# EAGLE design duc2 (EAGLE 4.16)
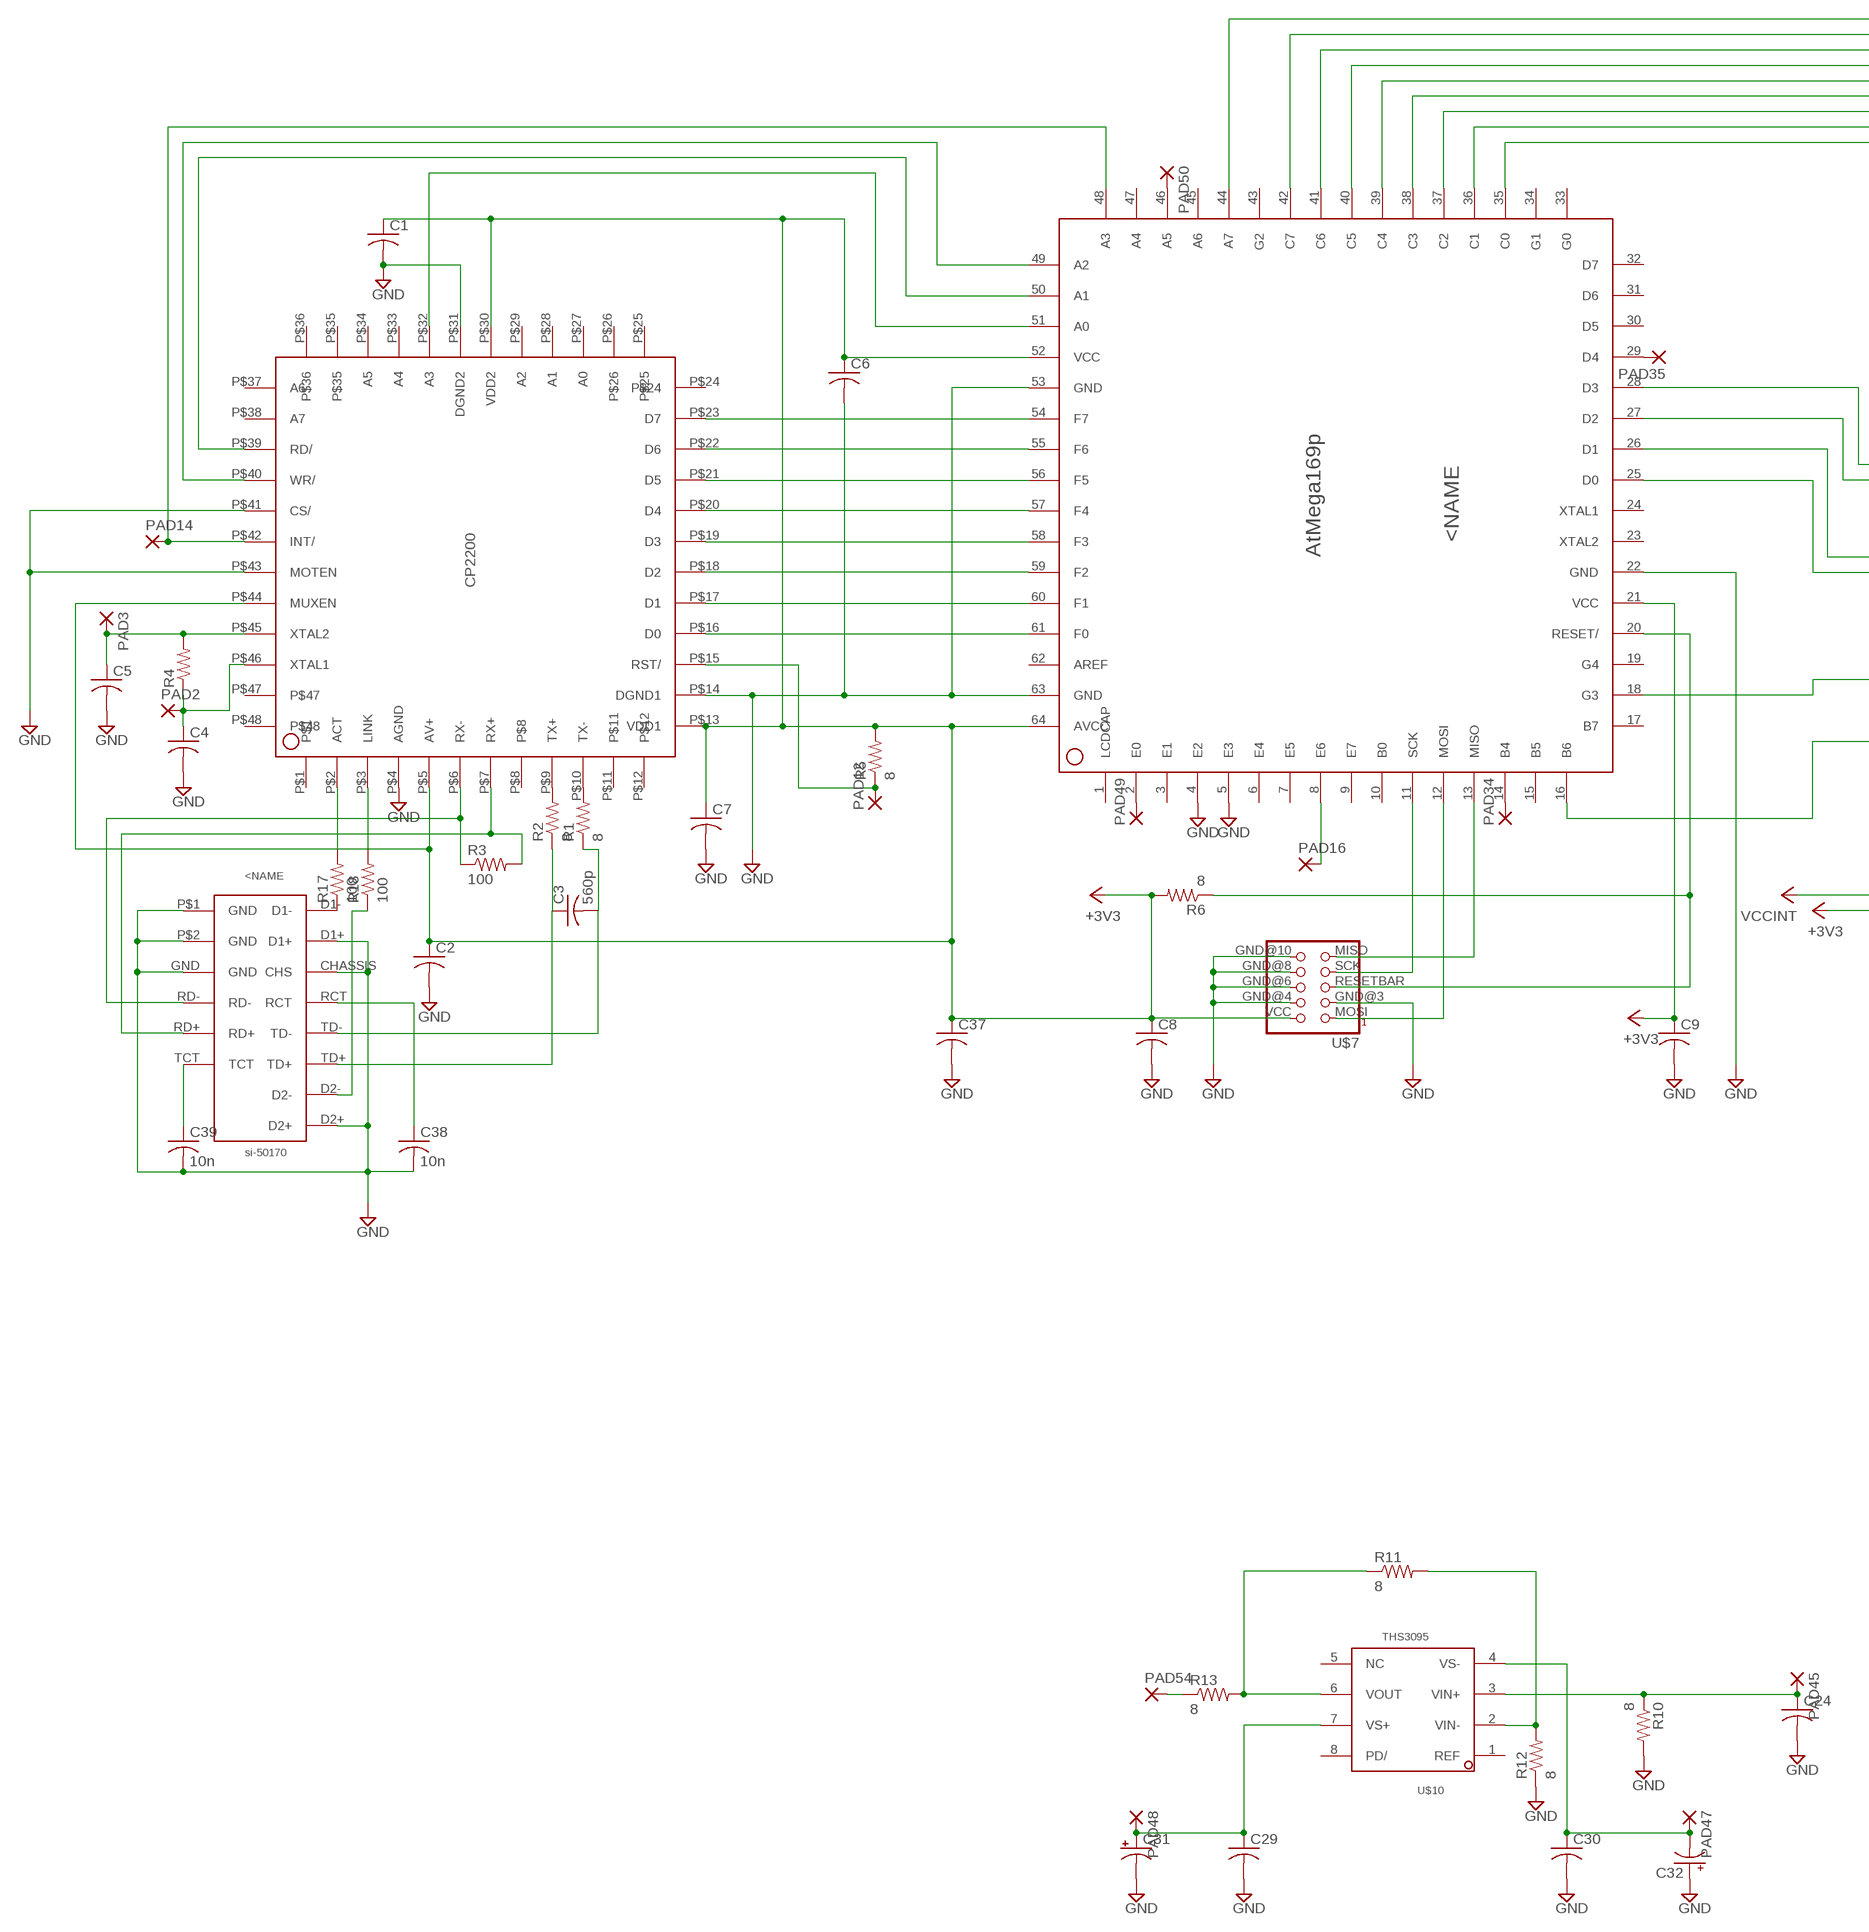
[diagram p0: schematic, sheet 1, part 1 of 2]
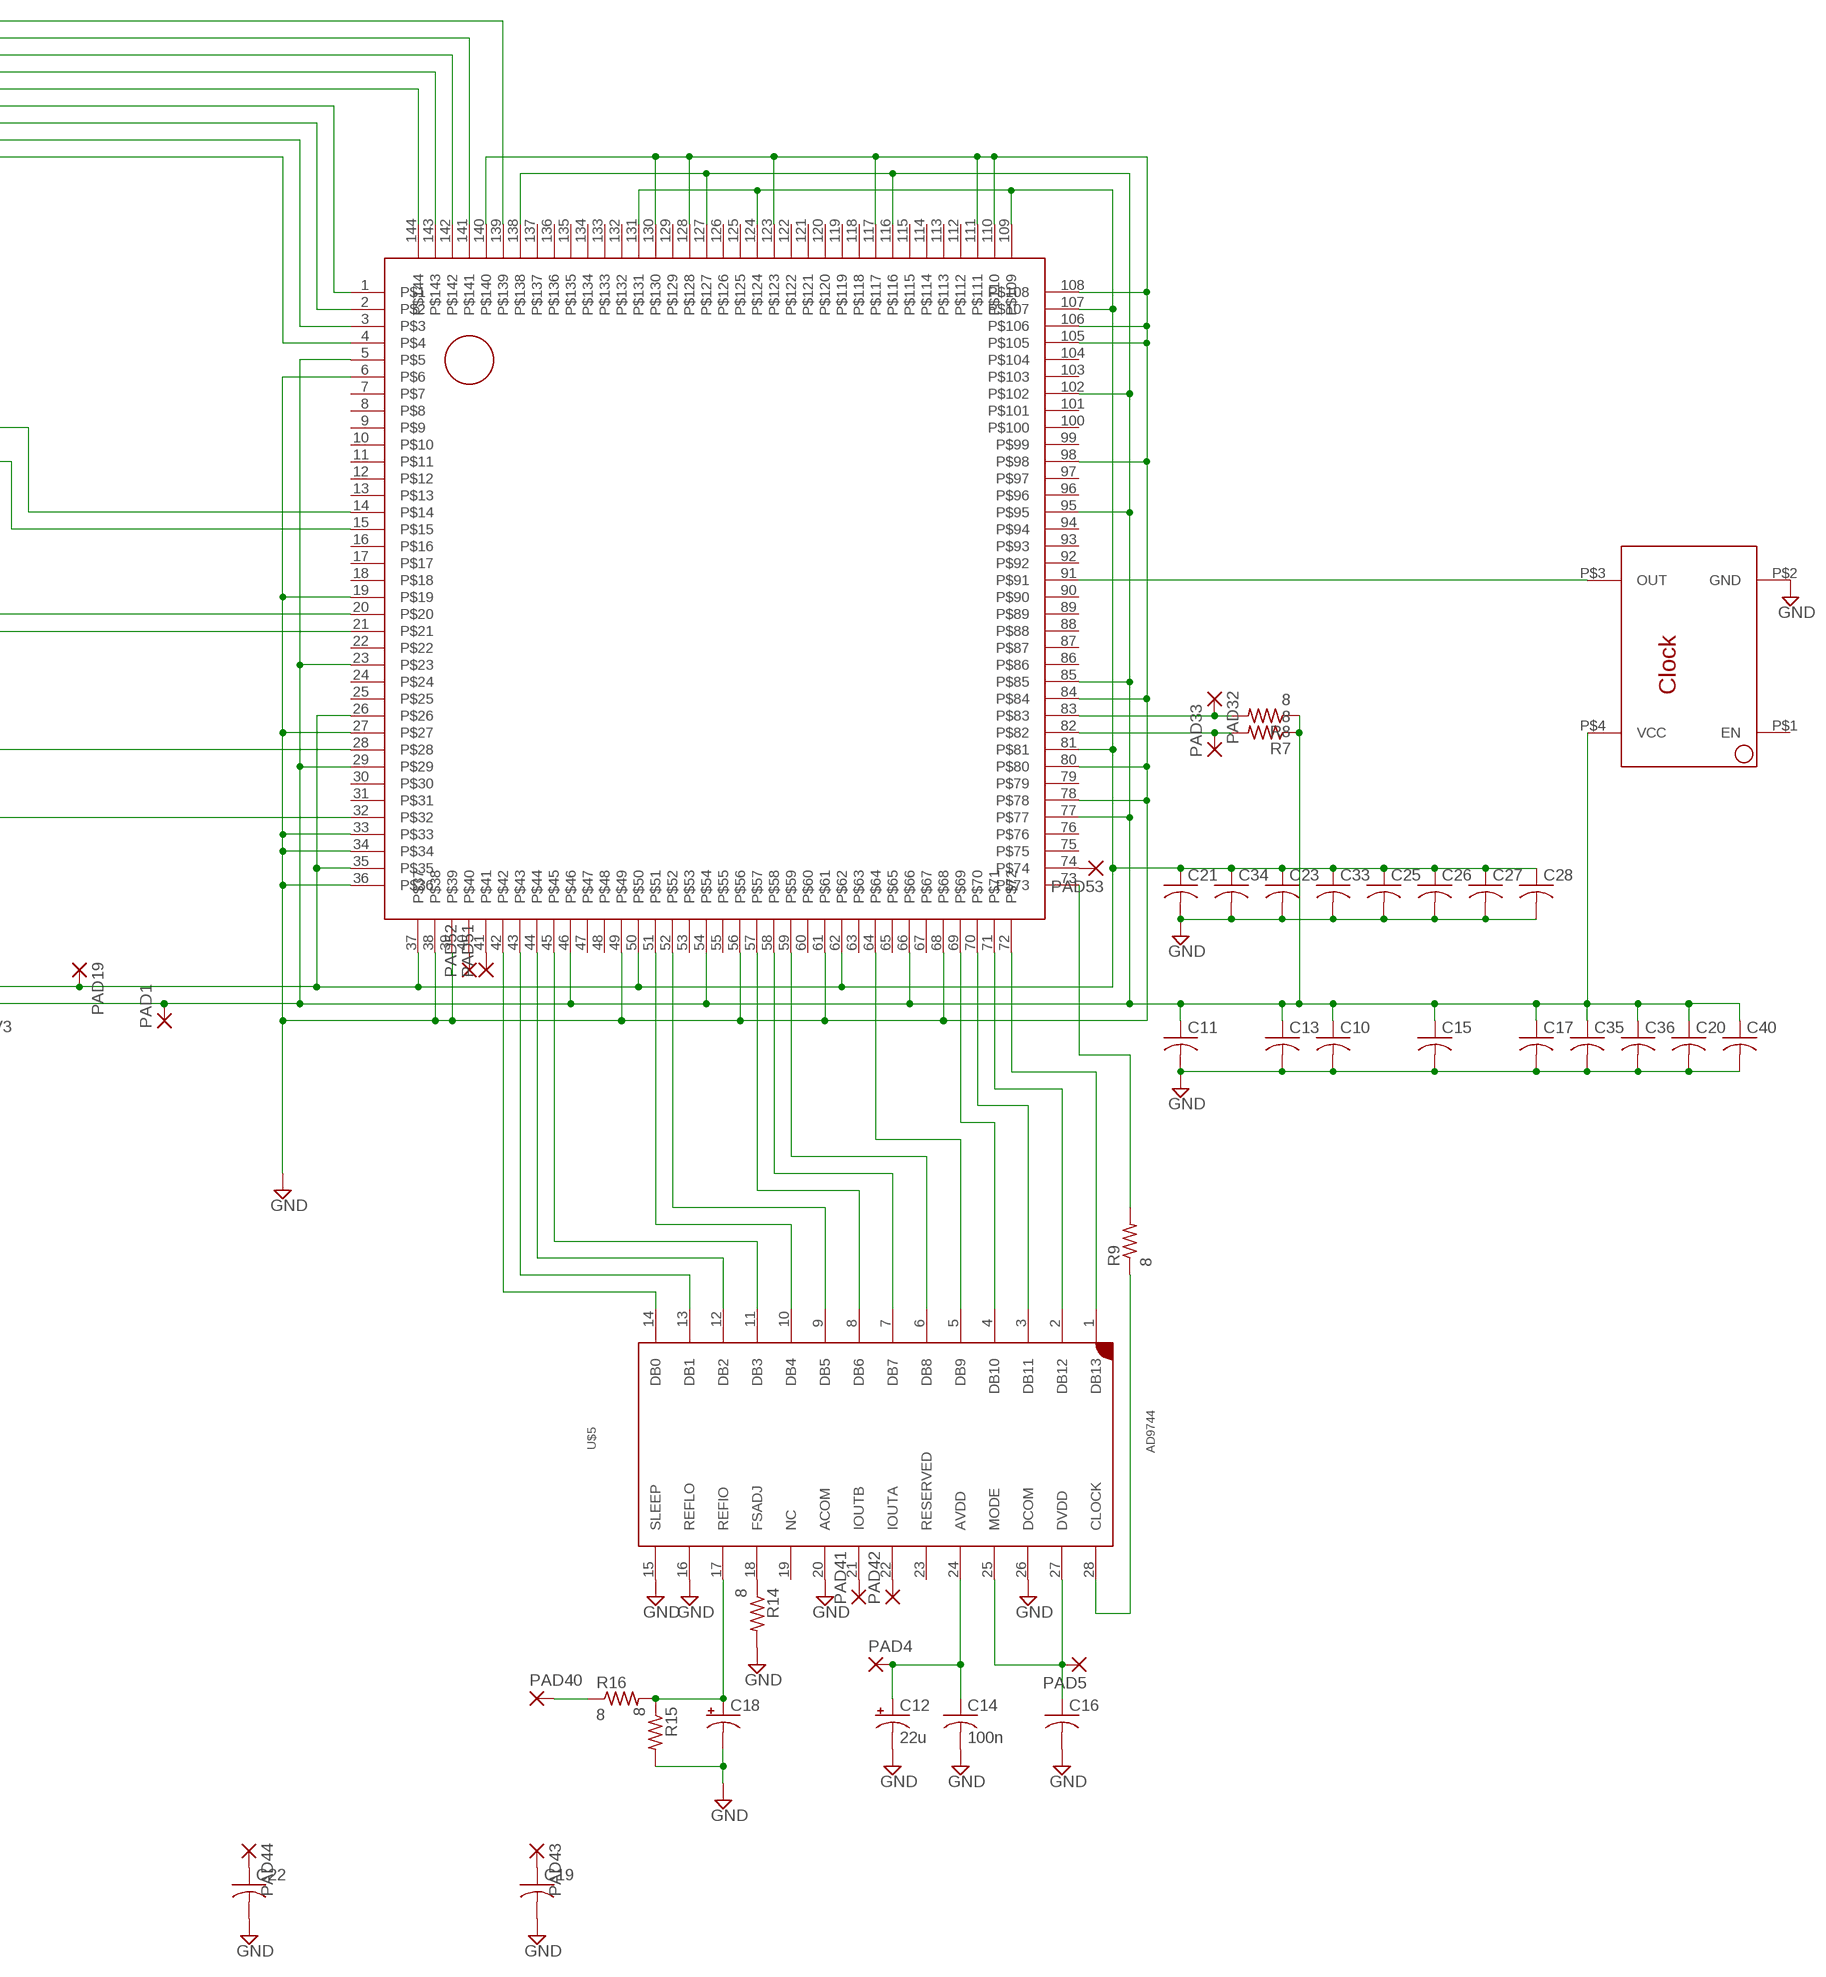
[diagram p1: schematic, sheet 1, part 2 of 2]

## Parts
C1  C-USC0805  [C0805]
C2  C-USC0805  [C0805]
C3  560p  C-USC1206  [C1206]
C4  C-USC1206  [C1206]
C5  C-USC1206  [C1206]
C6  C-USC0805  [C0805]
C7  C-USC0805  [C0805]
C8  C-USC0805  [C0805]
C9  C-USC0805  [C0805]
C10  C-USC0805  [C0805]
C11  C-USC0805  [C0805]
C12  22u  CPOL-USSMCB  [SMC_B]
C13  C-USC0805  [C0805]
C14  100n  C-USC0805  [C0805]
C15  C-USC0805  [C0805]
C16  C-USC0805  [C0805]
C17  C-USC0805  [C0805]
C18  CPOL-USSMCB  [SMC_B]
C19  C-USC1206  [C1206]
C20  C-USC0805  [C0805]
C21  C-USC0805  [C0805]
C22  C-USC1206  [C1206]
C23  C-USC0805  [C0805]
C24  C-USC1206  [C1206]
C25  C-USC0805  [C0805]
C26  C-USC0805  [C0805]
C27  C-USC0805  [C0805]
C28  C-USC0805  [C0805]
C29  C-USC0805  [C0805]
C30  C-USC0805  [C0805]
C31  CPOL-USD/7343-31W  [D/7343-31W]
C32  CPOL-USD/7343-31W  [D/7343-31W]
C33  C-USC0805  [C0805]
C34  C-USC0805  [C0805]
C35  C-USC0805  [C0805]
C36  C-USC0805  [C0805]
C37  C-USC0805  [C0805]
C38  10n  C-USC1206  [C1206]
C39  10n  C-USC1206  [C1206]
C40  C-USC0805  [C0805]
PAD1  SMD2  [SMD2]
PAD2  SMD2  [SMD2]
PAD3  SMD2  [SMD2]
PAD4  SMD2  [SMD2]
PAD5  SMD2  [SMD2]
PAD12  SMD2  [SMD2]
PAD14  SMD2  [SMD2]
PAD16  SMD2  [SMD2]
PAD19  SMD2  [SMD2]
PAD32  SMD2  [SMD2]
PAD33  SMD2  [SMD2]
PAD34  SMD2  [SMD2]
PAD35  SMD2  [SMD2]
PAD40  SMD2  [SMD2]
PAD41  SMD2  [SMD2]
PAD42  SMD2  [SMD2]
PAD43  SMD2  [SMD2]
PAD44  SMD2  [SMD2]
PAD45  SMD2  [SMD2]
PAD47  1,6/0,8  [1,6/0,8]
PAD48  1,6/0,8  [1,6/0,8]
PAD49  SMD2  [SMD2]
PAD50  SMD2  [SMD2]
PAD51  SMD2  [SMD2]
PAD52  SMD2  [SMD2]
PAD53  SMD2  [SMD2]
PAD54  SMD2  [SMD2]
R1  8  R-US_R1206  [R1206]
R2  8  R-US_R1206  [R1206]
R3  100  R-US_R1206  [R1206]
R4  R-US_R1206  [R1206]
R5  8  R-US_R1206  [R1206]
R6  8  R-US_R1206  [R1206]
R7  8  R-US_R1206  [R1206]
R8  8  R-US_R1206  [R1206]
R9  8  R-US_R1206  [R1206]
R10  8  R-US_R1206  [R1206]
R11  8  R-US_R1206  [R1206]
R12  8  R-US_R1206  [R1206]
R13  8  R-US_R1206  [R1206]
R14  8  R-US_R1206  [R1206]
R15  8  R-US_R1206  [R1206]
R16  8  R-US_R1206  [R1206]
R17  100  R-US_R1206  [R1206]
R18  100  R-US_R1206  [R1206]
U$1  CP2200  [MQFP48]
U$2  MEGA169P  [TQFP64]
U$3  EP2C8  [TQFP144]
U$4  MAGJACK2  [MAGJACK2]
U$5  AD9744  [TSSOP28]
U$6  CLOCKCB3  [CLOCKSMD]
U$7  AVR-ISP2X5SMD  [2X5SMD]
U$10  THS3095  [SOIC-8]

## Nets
+3V3: C1.1 C2.1 C6.1 C7.1 C8.1 C9.1 C10.1 C11.1 C13.1 C15.1 C17.1 C20.1 C35.1 C36.1 C37.1 C40.1 PAD1.1(P) R5.2 R6.2 R7.1 R8.1 U$1.P$5(AV+) U$1.P$13(VDD1) U$1.P$30(VDD2) U$1.P$44(MUXEN) U$2.21(VCC) U$2.52(VCC) U$2.64(AVCC) U$3.5 U$3.23 U$3.29 U$3.46 U$3.54 U$3.66 U$3.77 U$3.85 U$3.95 U$3.102 U$3.116 U$3.127 U$3.138 U$6.P$4(VCC) U$7.VCC
GND: C1.2 C2.2 C4.2 C5.2 C6.2 C7.2 C8.2 C9.2 C10.2 C11.2 C12.- C13.2 C14.2 C15.2 C16.2 C17.2 C18.- C19.2 C20.2 C21.2 C22.2 C23.2 C24.2 C25.2 C26.2 C27.2 C28.2 C29.2 C30.2 C31.- C32.+ C33.2 C34.2 C35.2 C36.2 C37.2 C38.2 C39.2 C40.2 R10.2 R12.1 R14.2 R15.2 U$1.P$4(AGND) U$1.P$14(DGND1) U$1.P$31(DGND2) U$1.P$41(CS/) U$1.P$43(MOTEN) U$2.4(E2) U$2.5(E3) U$2.22(GND) U$2.53(GND) U$2.63(GND) U$3.6 U$3.19 U$3.27 U$3.33 U$3.34 U$3.36 U$3.38 U$3.39 U$3.49 U$3.56 U$3.61 U$3.68 U$3.78 U$3.80 U$3.84 U$3.98 U$3.105 U$3.106 U$3.108 U$3.110 U$3.111 U$3.117 U$3.123 U$3.128 U$3.130 U$3.140 U$4.CHASSIS(CHS) U$4.D1+ U$4.D2+ U$4.GND U$4.P$1(GND) U$4.P$2(GND) U$5.15(SLEEP) U$5.16(REFLO) U$5.20(ACOM) U$5.26(DCOM) U$6.P$2(GND) U$7.GND@3 U$7.GND@4 U$7.GND@6 U$7.GND@8 U$7.GND@10
N$1: R1.2 U$1.P$10(TX-)
N$2: R2.2 U$1.P$9(TX+)
N$3: R17.1 U$4.D1-
N$4: PAD12.1(P) R5.1 U$1.P$15(RST/)
N$5: C16.1 PAD5.1(P) U$5.25(MODE) U$5.27(DVDD)
N$7: C5.1 PAD3.1(P) R4.2 U$1.P$45(XTAL2)
N$8: U$1.P$16(D0) U$2.61(F0)
N$9: R17.2 U$1.P$2(ACT)
N$10: C3.2 R1.1 U$4.TD-
N$11: R3.2 U$1.P$7(RX+) U$4.RD+
N$12: R18.1 U$4.D2-
N$13: C3.1 R2.1 U$4.TD+
N$14: U$1.P$17(D1) U$2.60(F1)
N$15: C4.1 PAD2.1(P) R4.1 U$1.P$46(XTAL1)
N$16: U$1.P$18(D2) U$2.59(F2)
N$17: U$1.P$19(D3) U$2.58(F3)
N$18: U$1.P$20(D4) U$2.57(F4)
N$19: U$1.P$21(D5) U$2.56(F5)
N$20: U$1.P$22(D6) U$2.55(F6)
N$21: U$1.P$23(D7) U$2.54(F7)
N$22: U$1.P$39(RD/) U$2.50(A1)
N$23: U$1.P$40(WR/) U$2.49(A2)
N$24: PAD14.1(P) U$1.P$42(INT/) U$2.48(A3)
N$26: R18.2 U$1.P$3(LINK)
N$27: U$2.13(MISO) U$7.MISO
N$28: U$2.11(SCK) U$7.SCK
N$29: U$2.12(MOSI) U$7.MOSI
N$30: R6.1 U$2.20(RESET/) U$7.RESETBAR
N$31: PAD16.1(P) U$2.8(E6)
N$32: PAD33.1(P) R7.2 U$3.82
N$33: PAD32.1(P) R8.2 U$3.83
N$34: U$1.P$32(A3) U$2.51(A0)
N$35: U$2.26(D1) U$3.20
N$36: U$2.27(D2) U$3.15
N$37: U$2.28(D3) U$3.14
N$38: U$2.44(A7) U$3.139
N$39: U$2.42(C7) U$3.141
N$40: U$2.41(C6) U$3.142
N$41: U$2.40(C5) U$3.143
N$42: R3.1 U$1.P$6(RX-) U$4.RD-
N$43: U$2.39(C4) U$3.144
N$44: U$2.38(C3) U$3.1
N$45: U$2.37(C2) U$3.2
N$46: U$2.36(C1) U$3.3
N$47: U$2.35(C0) U$3.4
N$48: PAD34.1(P) U$2.14(B4)
N$49: PAD35.1(P) U$2.29(D4)
N$50: U$3.91 U$6.P$3(OUT)
N$51: U$3.45 U$5.11(DB3)
N$52: U$3.43 U$5.13(DB1)
N$53: U$3.58 U$5.7(DB7)
N$54: U$3.59 U$5.6(DB8)
N$55: U$3.64 U$5.5(DB9)
N$56: U$3.44 U$5.12(DB2)
N$57: U$3.72 U$5.1(DB13)
N$58: R9.2 U$3.73
N$59: PAD51.1(P) U$3.41
N$60: U$3.52 U$5.9(DB5)
N$61: U$3.69 U$5.4(DB10)
N$62: U$3.57 U$5.8(DB6)
N$63: U$3.42 U$5.14(DB0)
N$64: U$3.51 U$5.10(DB4)
N$65: U$3.70 U$5.3(DB11)
N$66: U$3.71 U$5.2(DB12)
N$67: R9.1 U$5.28(CLOCK)
N$68: U$2.25(D0) U$3.21
N$69: U$2.18(G3) U$3.28
N$70: U$2.16(B6) U$3.32
N$71: C18.+ R15.1 R16.2 U$5.17(REFIO)
N$72: C12.+ C14.1 PAD4.1(P) U$5.24(AVDD)
N$74: R14.1 U$5.18(FSADJ)
N$75: PAD41.1(P) U$5.21(IOUTB)
N$76: PAD42.1(P) U$5.22(IOUTA)
N$77: C19.1 PAD43.1(P)
N$78: C22.1 PAD44.1(P)
N$79: C29.1 C31.+ PAD48.1(P) U$10.7(VS+)
N$80: C24.1 PAD45.1(P) R10.1 U$10.3(VIN+)
N$81: C30.1 C32.- PAD47.1(P) U$10.4(VS-)
N$82: R11.2 R12.2 U$10.2(VIN-)
N$83: R11.1 R13.2 U$10.6(VOUT)
N$84: PAD49.1(P) U$2.2(E0)
N$86: PAD50.1(P) U$2.46(A5)
N$88: C39.1 U$4.TCT
N$89: PAD52.1(P) U$3.40
N$90: PAD53.1(P) U$3.74
N$91: PAD54.1(P) R13.1
N$92: PAD40.1(P) R16.1
N$93: C38.1 U$4.RCT
VCCINT: C21.1 C23.1 C25.1 C26.1 C27.1 C28.1 C33.1 C34.1 PAD19.1(P) U$3.26 U$3.35 U$3.37 U$3.50 U$3.62 U$3.81 U$3.107 U$3.109 U$3.124 U$3.131
Unconnected: U$1.P$1 U$1.P$8 U$1.P$11 U$1.P$12 U$1.P$24 U$1.P$25 U$1.P$26 U$1.P$27(A0) U$1.P$28(A1) U$1.P$29(A2) U$1.P$33(A4) U$1.P$34(A5) U$1.P$35 U$1.P$36 U$1.P$37(A6) U$1.P$38(A7) U$1.P$47 U$1.P$48 U$2.1(LCDCAP) U$2.3(E1) U$2.6(E4) U$2.7(E5) U$2.9(E7) U$2.10(B0) U$2.15(B5) U$2.17(B7) U$2.19(G4) U$2.23(XTAL2) U$2.24(XTAL1) U$2.30(D5) U$2.31(D6) U$2.32(D7) U$2.33(G0) U$2.34(G1) U$2.43(G2) U$2.45(A6) U$2.47(A4) U$3.7 U$3.8 U$3.9 U$3.10 U$3.11 U$3.12 U$3.13 U$3.16 U$3.17 U$3.18 U$3.22 U$3.24 U$3.25 U$3.30 U$3.31 U$3.47 U$3.48 U$3.53 U$3.55 U$3.60 U$3.63 U$3.65 U$3.67 U$3.75 U$3.76 U$3.79 U$3.86 U$3.87 U$3.88 U$3.89 U$3.90 U$3.92 U$3.93 U$3.94 U$3.96 U$3.97 U$3.99 U$3.100 U$3.101 U$3.103 U$3.104 U$3.112 U$3.113 U$3.114 U$3.115 U$3.118 U$3.119 U$3.120 U$3.121 U$3.122 U$3.125 U$3.126 U$3.129 U$3.132 U$3.133 U$3.134 U$3.135 U$3.136 U$3.137 U$5.19(NC) U$5.23(RESERVED) U$6.P$1(EN) U$10.1(REF) U$10.5(NC) U$10.8(PD/)

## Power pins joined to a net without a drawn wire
AREF: U$2.62(AREF)

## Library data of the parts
C1-C11 C13-C17 C19-C30 C33-C40 = rcl:C-US: CAPACITOR, American symbol
C12 C18 C31 C32 = rcl:CPOL-US: POLARIZED CAPACITOR, American symbol
PAD1-PAD5 PAD12 PAD14 PAD16 PAD19 PAD32-PAD35 PAD40-PAD45 PAD49-PAD54 = wirepad:SMD2: SMD PAD
PAD47 PAD48 = wirepad:1,6/0,8: THROUGH-HOLE PAD
R1-R18 = rcl:R-US_: RESISTOR, American symbol
U$1 = Jim:CP2200
U$2 = Jim:MEGA169P
U$3 = Jim:EP2C8
U$4 = Jim:MAGJACK2
U$5 = Jim:AD9744
U$6 = Jim:CLOCKCB3
U$7 = Jim:AVR-ISP
U$10 = Jim:THS3095

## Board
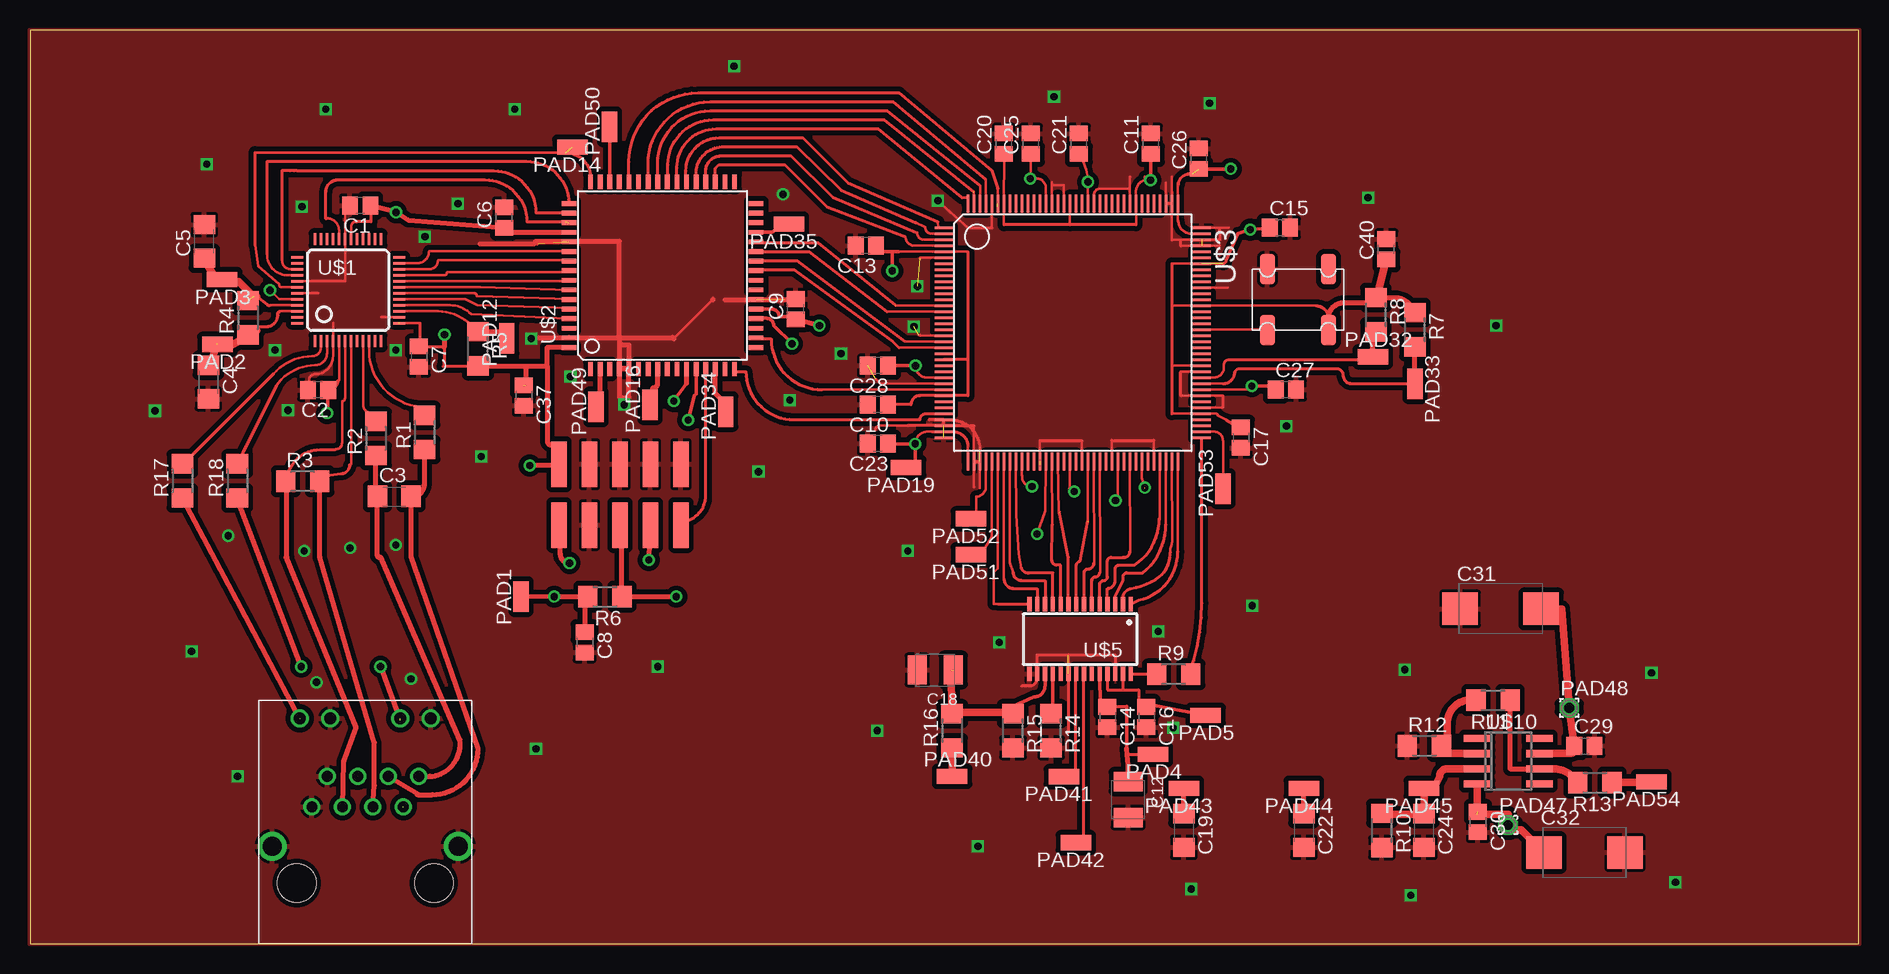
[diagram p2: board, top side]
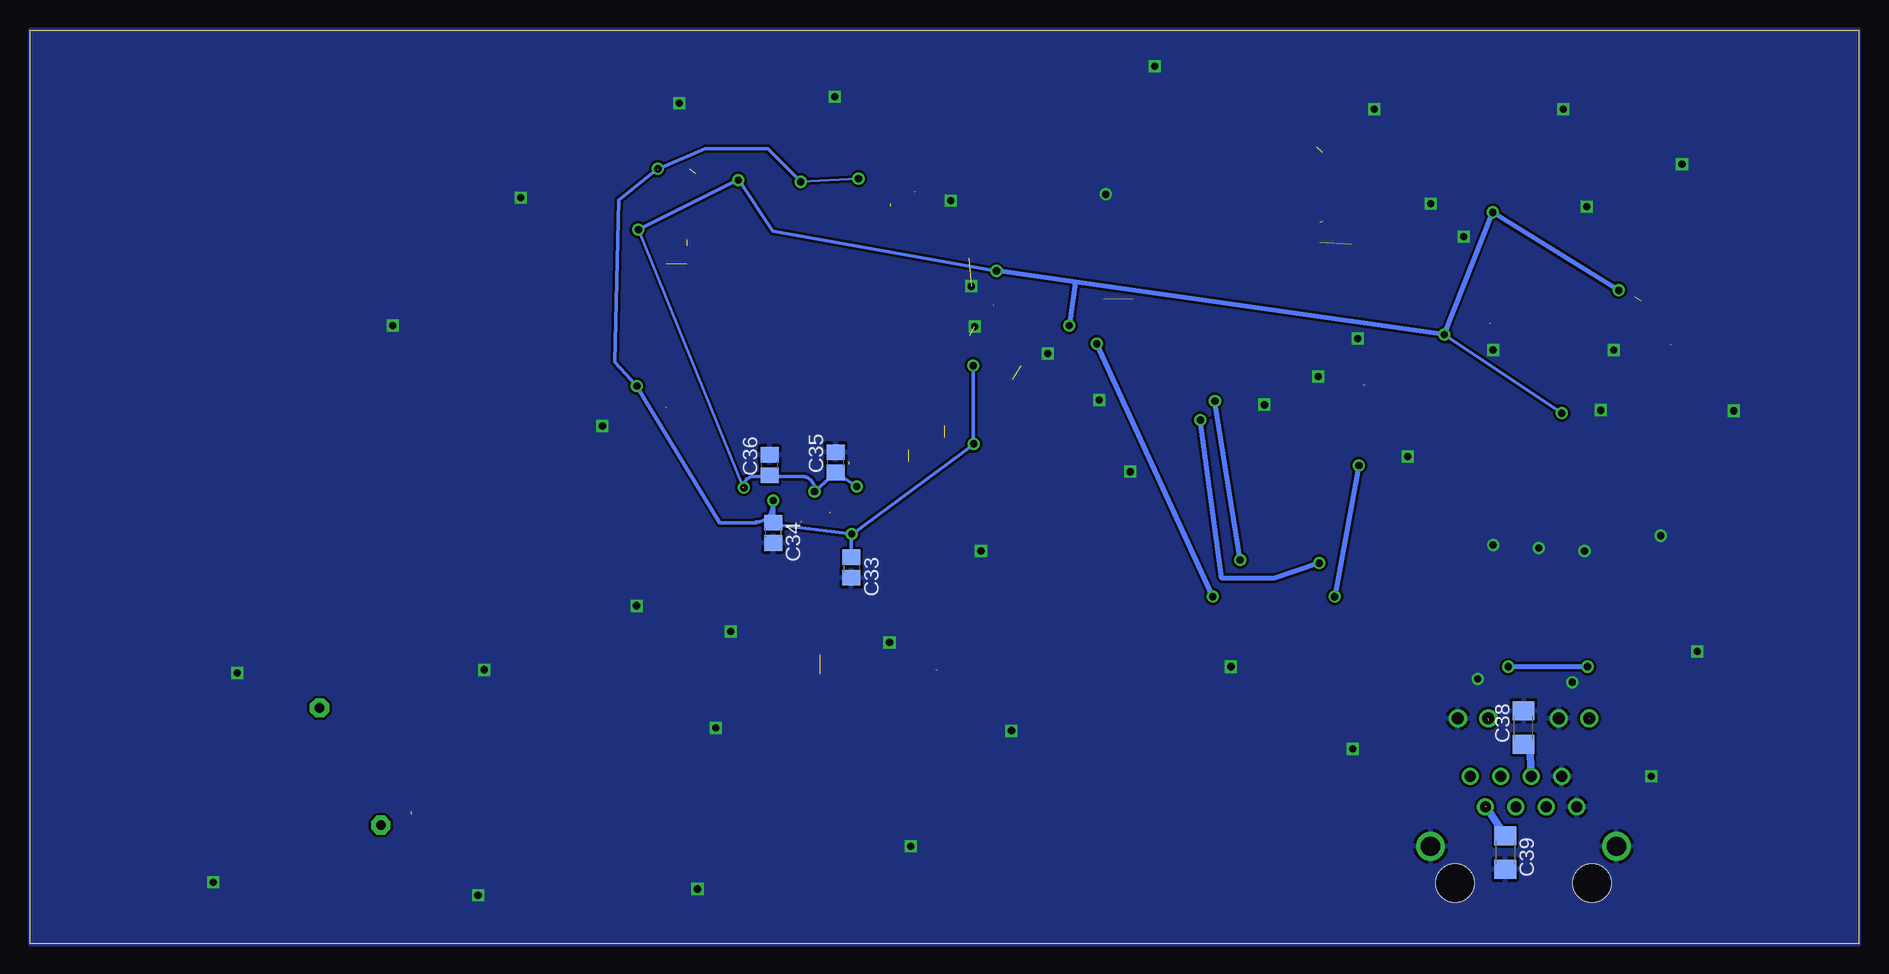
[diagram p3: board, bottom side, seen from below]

Size 152.4 x 76.2 mm. Coordinates in mm from the lower left corner, seen from the top.
Outline: 0,0 152.4,0 152.4,76.2 0,76.2 0,0
Copper layers (1*16): Top 0.035mm / dielectric 1.5mm / Bottom 0.035mm
Design rules "Jim": minimum track width 8mil, minimum drill 20mil, track to track 8mil, track to pad 8mil, pad to pad 8mil, via to via 8mil, smd to smd 8mil, copper to edge 0mil, drill to drill 10mil, minimum pad ring 10mil, minimum via ring 8mil, stop-mask expansion 0mil, vias tented up to drill 0mil, thermal gap 10mil

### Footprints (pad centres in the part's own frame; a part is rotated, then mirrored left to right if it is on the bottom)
C0805 = smd 1.3 x 1.5: 1 -0.85,0; 2 0.85,0
C1206 = smd 1.6 x 1.8: 1 -1.4,0; 2 1.4,0
SMC_B = smd 1.6 x 2.4: + -1.5,0; - 1.5,0
D/7343-31W = smd 2.95 x 2.7: + 3.375,0; - -3.375,0
SMD2 = smd 1.27 x 2.54: 1 0,0
1,6/0,8 = drill 0.813 pad 1.6 octagon: 1 0,0
R1206 = smd 1.6 x 1.803: 1 -1.422,0; 2 1.422,0
MQFP48 = smd 0.22 x 1: P$1 -2.75,-4.25; P$2 -2.25,-4.25; P$3 -1.75,-4.25; P$4 -1.25,-4.25; P$5 -0.75,-4.25; P$6 -0.25,-4.25; P$7 0.25,-4.25; P$8 0.75,-4.25; P$9 1.25,-4.25; P$10 1.75,-4.25; P$11 2.25,-4.25; P$12 2.75,-4.25; P$25 2.75,4.25; P$26 2.25,4.25; P$27 1.75,4.25; P$28 1.25,4.25; P$29 0.75,4.25; P$30 0.25,4.25; P$31 -0.25,4.25; P$32 -0.75,4.25; P$33 -1.25,4.25; P$34 -1.75,4.25; P$35 -2.25,4.25; P$36 -2.75,4.25 | smd 1 x 0.22: P$13 4.25,-2.75; P$14 4.25,-2.25; P$15 4.25,-1.75; P$16 4.25,-1.25; P$17 4.25,-0.75; P$18 4.25,-0.25; P$19 4.25,0.25; P$20 4.25,0.75; P$21 4.25,1.25; P$22 4.25,1.75; P$23 4.25,2.25; P$24 4.25,2.75; P$37 -4.25,2.75; P$38 -4.25,2.25; P$39 -4.25,1.75; P$40 -4.25,1.25; P$41 -4.25,0.75; P$42 -4.25,0.25; P$43 -4.25,-0.25; P$44 -4.25,-0.75; P$45 -4.25,-1.25; P$46 -4.25,-1.75; P$47 -4.25,-2.25; P$48 -4.25,-2.75
TQFP64 = smd 1.194 x 0.4: 1 -7.8,6; 2 -7.8,5.2; 3 -7.8,4.4; 4 -7.8,3.6; 5 -7.8,2.8; 6 -7.8,2; 7 -7.8,1.2; 8 -7.8,0.4; 9 -7.8,-0.4; 10 -7.8,-1.2; 11 -7.8,-2; 12 -7.8,-2.8; 13 -7.8,-3.6; 14 -7.8,-4.4; 15 -7.8,-5.2; 16 -7.8,-6; 33 7.8,-6; 34 7.8,-5.2; 35 7.8,-4.4; 36 7.8,-3.6; 37 7.8,-2.8; 38 7.8,-2; 39 7.8,-1.2; 40 7.8,-0.4; 41 7.8,0.4; 42 7.8,1.2; 43 7.8,2; 44 7.8,2.8; 45 7.8,3.6; 46 7.8,4.4; 47 7.8,5.2; 48 7.8,6 | smd 0.4 x 1.194: 17 -6,-7.8; 18 -5.2,-7.8; 19 -4.4,-7.8; 20 -3.6,-7.8; 21 -2.8,-7.8; 22 -2,-7.8; 23 -1.2,-7.8; 24 -0.4,-7.8; 25 0.4,-7.8; 26 1.2,-7.8; 27 2,-7.8; 28 2.8,-7.8; 29 3.6,-7.8; 30 4.4,-7.8; 31 5.2,-7.8; 32 6,-7.8; 49 6,7.8; 50 5.2,7.8; 51 4.4,7.8; 52 3.6,7.8; 53 2.8,7.8; 54 2,7.8; 55 1.2,7.8; 56 0.4,7.8; 57 -0.4,7.8; 58 -1.2,7.8; 59 -2,7.8; 60 -2.8,7.8; 61 -3.6,7.8; 62 -4.4,7.8; 63 -5.2,7.8; 64 -6,7.8
TQFP144 = smd 0.22 x 1.5: 1 -8.75,-10.75; 2 -8.25,-10.75; 3 -7.75,-10.75; 4 -7.25,-10.75; 5 -6.75,-10.75; 6 -6.25,-10.75; 7 -5.75,-10.75; 8 -5.25,-10.75; 9 -4.75,-10.75; 10 -4.25,-10.75; 11 -3.75,-10.75; 12 -3.25,-10.75; 13 -2.75,-10.75; 14 -2.25,-10.75; 15 -1.75,-10.75; 16 -1.25,-10.75; 17 -0.75,-10.75; 18 -0.25,-10.75; 19 0.25,-10.75; 20 0.75,-10.75; 21 1.25,-10.75; 22 1.75,-10.75; 23 2.25,-10.75; 24 2.75,-10.75; 25 3.25,-10.75; 26 3.75,-10.75; 27 4.25,-10.75; 28 4.75,-10.75; 29 5.25,-10.75; 30 5.75,-10.75; 31 6.25,-10.75; 32 6.75,-10.75; 33 7.25,-10.75; 34 7.75,-10.75; 35 8.25,-10.75; 36 8.75,-10.75; 73 8.75,10.75; 74 8.25,10.75; 75 7.75,10.75; 76 7.25,10.75; 77 6.75,10.75; 78 6.25,10.75; 79 5.75,10.75; 80 5.25,10.75; 81 4.75,10.75; 82 4.25,10.75; 83 3.75,10.75; 84 3.25,10.75; 85 2.75,10.75; 86 2.25,10.75; 87 1.75,10.75; 88 1.25,10.75; 89 0.75,10.75; 90 0.25,10.75; 91 -0.25,10.75; 92 -0.75,10.75; 93 -1.25,10.75; 94 -1.75,10.75; 95 -2.25,10.75; 96 -2.75,10.75; 97 -3.25,10.75; 98 -3.75,10.75; 99 -4.25,10.75; 100 -4.75,10.75; 101 -5.25,10.75; 102 -5.75,10.75; 103 -6.25,10.75; 104 -6.75,10.75; 105 -7.25,10.75; 106 -7.75,10.75; 107 -8.25,10.75; 108 -8.75,10.75 | smd 1.5 x 0.22: 37 10.75,-8.75; 38 10.75,-8.25; 39 10.75,-7.75; 40 10.75,-7.25; 41 10.75,-6.75; 42 10.75,-6.25; 43 10.75,-5.75; 44 10.75,-5.25; 45 10.75,-4.75; 46 10.75,-4.25; 47 10.75,-3.75; 48 10.75,-3.25; 49 10.75,-2.75; 50 10.75,-2.25; 51 10.75,-1.75; 52 10.75,-1.25; 53 10.75,-0.75; 54 10.75,-0.25; 55 10.75,0.25; 56 10.75,0.75; 57 10.75,1.25; 58 10.75,1.75; 59 10.75,2.25; 60 10.75,2.75; 61 10.75,3.25; 62 10.75,3.75; 63 10.75,4.25; 64 10.75,4.75; 65 10.75,5.25; 66 10.75,5.75; 67 10.75,6.25; 68 10.75,6.75; 69 10.75,7.25; 70 10.75,7.75; 71 10.75,8.25; 72 10.75,8.75; 109 -10.75,8.75; 110 -10.75,8.25; 111 -10.75,7.75; 112 -10.75,7.25; 113 -10.75,6.75; 114 -10.75,6.25; 115 -10.75,5.75; 116 -10.75,5.25; 117 -10.75,4.75; 118 -10.75,4.25; 119 -10.75,3.75; 120 -10.75,3.25; 121 -10.75,2.75; 122 -10.75,2.25; 123 -10.75,1.75; 124 -10.75,1.25; 125 -10.75,0.75; 126 -10.75,0.25; 127 -10.75,-0.25; 128 -10.75,-0.75; 129 -10.75,-1.25; 130 -10.75,-1.75; 131 -10.75,-2.25; 132 -10.75,-2.75; 133 -10.75,-3.25; 134 -10.75,-3.75; 135 -10.75,-4.25; 136 -10.75,-4.75; 137 -10.75,-5.25; 138 -10.75,-5.75; 139 -10.75,-6.25; 140 -10.75,-6.75; 141 -10.75,-7.25; 142 -10.75,-7.75; 143 -10.75,-8.25; 144 -10.75,-8.75
MAGJACK2 = drill 0.9 round: CHASSIS 8.89,3.175; GND 6.35,4.445; RCT 8.89,0.635; RD+ 6.35,-0.635; RD- 6.35,1.905; TCT 6.35,-3.175; TD+ 8.89,-4.445; TD- 8.89,-1.905 | drill 1 round: D1+ 13.716,2.921; D1- 13.716,5.461; D2+ 13.716,-5.461; D2- 13.716,-2.921 | drill 1.6 round: P$1 3.048,7.747; P$2 3.048,-7.747 | hole 3.2: 0,5.715; 0,-5.715
TSSOP28 = smd 0.35 x 1.2: 1 -4.225,-2.9; 2 -3.575,-2.9; 3 -2.925,-2.9; 4 -2.275,-2.9; 5 -1.625,-2.9; 6 -0.975,-2.9; 7 -0.325,-2.9; 8 0.325,-2.9; 9 0.975,-2.9; 10 1.625,-2.9; 11 2.275,-2.9; 12 2.925,-2.9; 13 3.575,-2.9; 14 4.225,-2.9; 15 4.225,2.9; 16 3.575,2.9; 17 2.925,2.9; 18 2.275,2.9; 19 1.625,2.9; 20 0.975,2.9; 21 0.325,2.9; 22 -0.325,2.9; 23 -0.975,2.9; 24 -1.625,2.9; 25 -2.275,2.9; 26 -2.925,2.9; 27 -3.575,2.9; 28 -4.225,2.9
CLOCKSMD = smd 1.27 x 2.54: P$1 -2.54,-2.54; P$2 2.54,-2.54; P$3 2.54,2.54; P$4 -2.54,2.54
2X5SMD = smd 1.27 x 3.81: GND@3 -2.54,-2.54; GND@4 -2.54,2.54; GND@6 0,2.54; GND@8 2.54,2.54; GND@10 5.08,2.54; MISO 5.08,-2.54; MOSI -5.08,-2.54; RESETBAR 0,-2.54; SCK 2.54,-2.54; VCC -5.08,2.54
SOIC-8 = smd 0.6 x 2.2: 1 -1.905,-2.6; 2 -0.635,-2.6; 3 0.635,-2.6; 4 1.905,-2.6; 5 1.905,2.6; 6 0.635,2.6; 7 -0.635,2.6; 8 -1.905,2.6

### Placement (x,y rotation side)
C1  27.51,61.56 180 top
C2  24,46.19 180 top
C3  30.35,37.32 0 top
C4  14.87,46.85 270 top
C5  14.53,58.57 90 top
C6  39.51,60.56 90 top
C7  32.41,48.96 270 top
C8  46.23,25.15 270 top
C9  63.81,52.91 90 top
C10  70.66,44.96 180 top
C11  93.41,66.71 90 top
C12  91.51,12.03 270 top
C13  69.66,58.21 180 top
C14  89.78,18.91 270 top
C15  104.16,59.71 0 top
C16  93.03,18.91 270 top
C17  100.91,42.21 270 top
C18  75.43,22.84 180 top
C19  96.16,9.46 270 top
C20  81.16,66.71 90 top
C21  87.41,66.71 90 top
C22  106.16,9.46 270 top
C23  70.66,41.71 180 top
C24  116.16,9.46 270 top
C25  83.41,66.71 90 top
C26  97.41,65.46 90 top
C27  104.66,46.21 0 top
C28  70.66,48.21 180 top
C29  129.54,16.51 0 top
C30  120.65,10.16 270 top
C31  122.56,27.94 0 top
C32  129.54,7.62 0 top
C33  83.95,31.38 270 bottom
C34  90.48,34.28 270 bottom
C35  85.27,40.15 90 bottom
C36  90.75,39.92 90 bottom
C37  41.15,45.72 270 top
C38  27.94,18.03 90 bottom
C39  29.46,7.62 270 bottom
C40  113.03,57.91 90 top
PAD1  40.92,28.97 0 top
PAD2  15.62,50 90 top
PAD3  16.01,55.39 90 top
PAD4  93.58,15.81 90 top
PAD5  97.97,19.06 90 top
PAD12  39.72,50.51 0 top
PAD14  45.19,66.42 90 top
PAD16  51.66,44.96 0 top
PAD19  73.01,39.72 90 top
PAD32  111.91,48.96 270 top
PAD33  115.41,46.71 180 top
PAD34  57.97,44.38 0 top
PAD35  63.24,60.02 90 top
PAD40  76.83,13.97 270 top
PAD41  86.16,13.96 90 top
PAD42  87.16,8.46 90 top
PAD43  96.16,12.97 90 top
PAD44  106.16,12.97 90 top
PAD45  116.16,12.97 90 top
PAD47  123.16,9.91 0 top
PAD48  128.27,19.68 0 top
PAD49  47.17,44.78 0 top
PAD50  48.29,68.12 0 top
PAD51  78.41,32.46 90 top
PAD52  78.41,35.46 90 top
PAD53  99.41,37.96 0 top
PAD54  135.11,13.52 90 top
R1  32.89,42.65 90 top
R2  28.83,42.15 90 top
R3  22.73,38.57 0 top
R4  18.16,52.21 90 top
R5  37.33,49.63 270 top
R6  47.91,28.96 180 top
R7  115.41,51.21 270 top
R8  112.16,52.46 270 top
R9  95.31,22.48 0 top
R10  112.66,9.46 270 top
R11  121.92,20.32 180 top
R12  116.2,16.51 0 top
R13  130.41,13.46 180 top
R14  85.09,17.78 270 top
R15  81.92,17.78 270 top
R16  76.83,17.78 90 top
R17  12.7,38.61 90 top
R18  17.27,38.61 90 top
U$1  26.5,54.5 0 top
U$2  52.71,55.73 90 top
U$3  86.91,50.96 270 top
U$4  27.94,5.08 90 top
U$5  87.51,25.41 180 top
U$6  105.66,53.71 180 top
U$7  49.16,37.46 0 top
U$10  123.19,15.24 270 top

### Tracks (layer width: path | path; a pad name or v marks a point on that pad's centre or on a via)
+3V3  (via drill 0.6)  (4 unrouted)
  Top 0.22: C20.1 81.18,65.69 U$3.138 81.16,60 81.16,59.96 | 92.16,59.96 92.17,59.95 U$3.116 92.16,62.73 arc-90 93.12,63.69 arc-90 92.91,63.89 92.91,63.96 | 86.66,59.96 86.66,59.96 arc-90 86.66,59.96 U$3.127 | 99.41,56.71 99.41,56.72 arc90 99.41,56.73 arc-90 99.39,56.71 95.16,56.71 | U$3.95 arc-90 U$3.95 arc90 U$3.95 | 95.16,53.21 U$3.95 | U$3.95 | 107.23,53.21 arc90 107.26,53.24 arc-90 107.23,53.21 | 107.23,53.21 107.16,53.21 | U$3.95 107.23,53.21 | 95.16,48.21 95.17,48.21 arc-90 95.18,48.2 arc-90 95.19,48.21 U$3.85 | 95.16,44.21 95.16,44.18 arc-90 95.15,44.16 arc-90 95.19,44.21 U$3.77 98.83,44.21 arc-90 98.98,44.06 99.71,43.69 99.71,43.68 | 86.66,37.96 86.66,38.05 U$3.54 | U$3.46 82.66,39.07 arc90 82.67,39.06 82.67,38.92 arc90 83.46,38.13 v83.5,38.13 | 78.16,57.66 78.19,57.66 arc90 78.14,57.71 U$3.5 72.43,57.71 arc90 72.43,57.7 arc90 72.42,57.71 72.41,57.71 | 32.51,51.76 32.5,51.76 | 32.5,51.76 30.71,51.76 | 32.5,51.76 32.5,51.75 | 25.66,46.96 25.75,47 U$1.P$5 | U$3.66 | U$3.66 92.66,38.85 v92.91,38.03 v92.91,38.04 | U$1.P$44 20.75,53.75 v20,54.5 | 27.25,60.21 27.25,60.25 arc90 26.75,59.75 U$1.P$30
  Top 0.254: 78.16,48.71 78.16,45.71 U$3.29 74.16,45.71 arc90 73.41,44.96 C10.1 71.41,44.96 | 78.16,48.71 78.16,57.66 78.16,57.71 | 78.16,48.71 U$3.23 | 81.16,59.96 86.66,59.96 92.16,59.96 | 95.16,44.21 95.16,48.21 95.16,53.21 95.16,56.71 | C11.1 93.41,65.96 | C17.1 100.91,42.96 99.71,43.68 99.66,43.71 | U$6.P$4 108.2,52.17 arc90 107.16,53.21 | 99.41,56.71 arc90 99.66,56.96 100.66,59.21 | 32.46,49.76 32.51,49.76 32.51,51.76 | 32.46,49.76 C7.1 | 32.46,49.76 34.51,49.76 34.51,48.56 | 34.43,48.16 34.54,48.16 37.33,48.16 | C2.1 24.89,46.19 arc90 24.91,46.21 arc90 25.66,46.96 | 27.16,60.21 27.25,60.21 28.41,60.21 28.41,61.46 arc-90 28.36,61.51 C1.1
  Top 0.305: C13.1 arc-90 70.57,58.15 70.57,57.72 71.81,57.72 | 72.41,57.71 arc90 72.4,57.72 71.81,57.72 | 71.81,57.72 arc-90 71.86,57.68 v71.86,56.12 | 93.12,63.69 93.24,63.73 v93.38,63.69 93.39,63.69 C11.1 | C15.1 103.34,59.67 v101.7,59.56 101.66,59.56 100.66,59.21 | 86.66,37.96 86.7,37.98 v87.02,37.72 | 34.54,48.16 34.54,48.26 arc-90 34.51,48.29 34.51,48.56 | U$2.21 61.81,52.93 arc-90 62.43,52.31 63.76,52.31 arc-90 63.81,52.26 C9.1 | v24.75,44.25 C2.1
  Top 0.406: 70.41,57.96 70.51,58.06 C13.1 | 108.2,52.17 arc-90 109.49,53.46 112.16,53.46 R8.1 113.74,53.88 arc-90 115.41,52.21 R7.1 | U$2.64 44.91,49.76 43.11,49.76 43.11,48.16 | R5.2 37.33,48.16 41.31,48.16 | 41.31,48.16 43.11,48.16 | 43.11,48.16 43.11,41.96 arc90 43.51,41.56 43.91,41.56 43.91,40.36 | 43.91,40 43.91,39.96 | 43.91,40.36 43.91,40 | 43.91,40 U$7.VCC 43.94,39.88 v41.66,39.88 | 43.91,40.36 43.91,40.14 | 41.31,48.16 41.31,46.61 | 34.51,49.76 34.51,50.77 arc-90 v34.54,50.8 | C8.1 46.23,28.96 R6.2 v43.69,28.96 40.92,28.93 PAD1.1 | v65.79,51.56 C9.1 | U$2.52 39.74,59.33 arc-90 39.71,59.36 arc-90 39.72,59.35 C6.1 31.51,60.36 v30.5,61 C1.1
  Top 0.61: R8.1 112.27,54.1 C40.1
  Bottom 0.22: v101.7,59.56 101.7,59.6 92.96,38.06 92.92,37.98
  Bottom 0.305: v71.86,56.12 90.5,59.45 93.36,63.77 93.37,63.73 | 93.37,63.73 v93.38,63.69 | 93.37,63.73 v101.7,59.56 | 92.96,38.06 arc90 92.03,38.99 90.93,38.99 | 90.93,38.99 88.08,38.99 arc90 87.02,37.92 v87.02,37.72 v87.01,37.72 85.25,39.32 C35.1 v83.5,38.12 v83.5,38.13 | 90.93,38.99 90.93,38.98 C36.1 | v34.54,50.8 34.5,50.75 v24.75,44.25
  Bottom 0.406: v71.86,56.12 71.88,56.13 65.27,55.19 | 65.27,55.19 v34.54,50.8 v30.5,61 v20,54.5 | v41.66,39.88 v43.69,28.96 | 65.27,55.19 65.28,55.12 v65.79,51.56
GND  (via drill 0.6)  (11 unrouted)
  Top 0.22: C2.2 arc-90 23.21,46.25 23.25,46.25 23.25,47 arc-90 23.75,47.5 arc90 25.25,49 U$1.P$4 25.25,51.75 | 29.25,52.25 U$1.P$14 | C1.2 26.31,61.56 arc90 26.25,61.5 U$1.P$31 26.25,55.25 U$1.P$41 | U$1.P$43 24,54.25 | 80.16,59.71 U$3.140 | 85.16,63.52 U$3.130 85.16,63.26 86.16,63.25 U$3.128 | 85.16,63.52 arc-90 85.16,63.52 | 91.66,62.97 U$3.117 | 91.66,62.97 91.66,63.98 arc-90 91.67,63.99 | 95.18,58.71 95.18,58.69 arc-90 95.16,58.71 | 95.16,58.71 95.16,62.71 95.16,63.96 arc90 95.15,63.97 | U$3.111 94.65,63.47 94.64,63.47 94.64,63.45 | U$3.108 99.16,59.71 99.89,59.71 arc-90 99.9,59.71 | 99.16,58.71 arc90 99.17,58.72 arc-90 99.16,58.71 | 99.16,58.71 99.17,58.75 | 99.16,58.71 U$3.106 95.16,58.71 | 95.16,58.71 arc90 95.15,58.72 arc90 95.16,58.71 | 95.16,58.71 | 95.91,58.21 95.91,58.2 arc90 95.91,58.2 arc-90 95.92,58.21 99.16,58.21 | U$3.98 99.82,54.71 arc90 99.82,54.71 | 95.91,47.71 arc90 95.9,47.7 arc-90 95.91,47.71 | 95.91,47.69 95.91,47.71 | 95.91,47.71 U$3.84 | 99.41,45.71 arc90 99.41,45.71 arc-90 99.41,45.71 | 99.41,45.71 99.41,45.69 | 99.41,45.71 U$3.80 95.93,45.71 arc-90 95.92,45.71 arc-90 95.92,45.71 95.91,45.71 | U$3.78 99.39,44.71 | 93.65,41.98 93.65,42.01 U$3.68 | 90.16,41.98 90.16,42.01 U$3.61 | 87.66,41.96 87.65,41.96 U$3.56 | 84.16,41.96 84.15,41.96 84.16,39.96 | 78.66,43.21 78.66,38.1 arc90 78.67,38.09 | 79.16,41.21 79.16,38.03 arc-90 79.16,38.03 | U$3.6 74.19,57.21 arc90 74.17,57.19 | U$3.19 74.2,50.71 arc90 74.08,50.77 | U$3.27 70.87,46.71 70.5,47.08 | U$3.34 70.83,43.21 arc90 70.44,42.82 | U$3.123 88.66,62.45 arc-90 89.2,62.98 91.64,62.98 arc-90 91.65,62.97 91.66,62.97
  Top 0.254: 53.66,50.46 56.91,53.71 | 23.16,46.21 23.15,46.21 C2.2 | U$3.33 76.66,43.71 arc-90 79.16,41.21 | U$3.33 74.91,43.71 | U$3.34 73.16,43.21 | U$3.34 78.66,43.21 | U$3.38 U$3.39 | U$3.34 U$3.33 | 95.16,62.71 U$3.110 U$3.111 | C1.2 26.66,61.46 | 42.11,58.56 arc90 42.31,58.36 | 80.16,59.71 78.16,59.71 75.91,61.71 v75.66,61.96 | 90.11,41.98 90.16,41.98 93.65,41.98 93.69,41.98 | 84.16,41.96 87.66,41.96 | U$5.20 86.53,22.48 | 99.41,45.69 99.41,44.73 | 95.91,45.71 95.91,47.69 | U$5.26 90.44,24.11 86.53,24.11 | 86.53,24.11 86.53,17.61 | 86.53,24.11 83.94,24.11 83.94,22.16 arc-90 83.28,21.51 82.64,21.51 | 99.17,58.75 99.16,59.71 | 95.91,58.21 95.91,58.71 | 95.18,58.71 95.16,58.71
  Top 0.406: C2.2 23.41,46.19 | U$2.22 60.54,53.76 | 56.91,53.71 56.91,53.76 | 53.66,50.46 53.56,50.56 49.11,50.56 | 44.91,50.56 49.11,50.56 | 49.11,50.56 49.11,58.56 42.11,58.56 arc-90 41.91,58.36 37.51,58.36 | U$2.53 44.94,58.56 | 44.91,50.56 U$2.63 | 42.11,50.56 44.91,50.56 | 49.11,50.56 49.11,49.96 | 49.11,49.96 U$2.4 | U$2.4 49.11,45.56 49.91,45.56 U$2.5 49.91,47.96 | 49.91,47.96 49.91,49.96 49.11,49.96 | U$2.4 arc-90 49.14,47.96 49.91,47.96 | C9.2 62.91,53.71 57.91,53.71
  other vias: 22.66,61.46 35.66,61.71 32.91,58.96 45.04,47.3 73.66,51.46 73.95,54.83 94.01,26.06 20.42,49.52 67.58,49.23 63.31,45.35 41.76,50.47 49.53,44.96 21.5,44.5 22.86,32.77 30.48,33.27 16.51,34.04 26.67,33.02 23.88,21.82 31.75,22.09 30.48,49.51 14.73,65.02 24.64,69.6 40.39,69.6 37.59,40.64 10.41,44.45 13.46,24.38 60.71,39.37 58.67,73.17 85.34,70.64 73.15,32.77 80.77,25.15 104.7,43.17 111.51,62.23 101.85,28.19 122.17,51.56 135.13,22.61 115.06,4.06 96.77,4.57 78.99,8.13 114.55,22.86 95.26,18.01 98.3,70.1 70.61,17.78 52.32,23.11 17.3,13.97 42.16,16.26 137.12,5.13 62.75,62.5
  pour Top (isolate 0.406): 0,0 0,76.2 152.4,76.2 152.4,0
  pour Bottom: 0,0 0,76.2 152.4,76.2 152.4,0
N$1
  Top 0.22: U$1.P$10 28.25,49.5 arc90 33,44.75 33,44 arc90 32.93,44.07 R1.2
N$2
  Top 0.22: U$1.P$9 27.75,45 arc90 28.5,44.25 28.5,43.75 arc90 28.75,43.5 arc-90 R2.2
  Top 0.254: 28.5,43.75 arc90 28.75,43.5
N$3  (1 unrouted)
  Top 0.406: 22.48,18.78 R17.1
N$4
  Top 0.22: U$1.P$15 34,52.75 arc-57 37.25,51 R5.1
  Top 0.254: 37.31,50.96 37.31,51.05 R5.1
  Top 0.406: PAD12.1 39.71,51.05 R5.1
N$5
  Top 0.254: 91.08,21.18 U$5.27 | 91.08,21.18 92.39,21.18 92.39,19.56 93.03,19.56 C16.1 | U$5.25 89.78,21.18 91.08,21.18
  Top 0.305: C16.1 93,20 PAD5.1
N$7  (1 unrouted)
  Top 0.22: 19.91,53.21 20,53.21 20,53.25 U$1.P$45
  Top 0.254: 18.91,53.96 arc90 18.91,53.96 19.79,53.3 | 19.79,53.3 19.91,53.21 | 19.79,53.3 19.79,53.3 arc-90 19.79,53.3 arc90 19.84,53.25
  Top 0.61: 18.91,53.96 18.66,53.96 17.41,55.21 16.41,55.21 16.38,55.18 PAD3.1 15.79,55.08 15.66,55.21 14.41,57.21 C5.1
N$8
  Top 0.22: U$1.P$16 35,53.25 arc-46 36.75,52.5 44.75,52.14 U$2.61 44.5,52.13
  Top 0.254: 44.71,52.16 arc90 44.74,52.13 U$2.61
N$9
  Top 0.22: U$1.P$2 24.25,49.75 arc-90 23.5,49 arc50 20.25,47.5
  Top 0.305: R17.2 12.75,40 20.25,47.5
N$10
  Top 0.406: R1.1 32.89,38.44 arc-90 31.66,37.21 arc90 31.75,37.3 C3.2 31.75,32.26 37.34,16.26 arc-90 33.53,12.45 32.3,12.45 | 32.3,12.45 32.26,12.45 | 32.3,12.45 32.3,12.49 U$4.TD-
N$11
  Top 0.22: 26.66,39.96 26.71,39.96 arc90 26.75,40 U$1.P$7
  Top 0.254: 26.66,39.96 arc-90 25.91,39.21 24.16,38.96 R3.2
  Top 0.406: 24.15,32.22 arc-90 24.16,32.21 arc-90 24.15,32.22 24.15,32.26 | 24.15,32.26 R3.2 | 24.15,32.26 24.13,32.26 28.7,16.76 28.7,13.21 U$4.RD+
N$12  (via drill 0.6)  (1 unrouted)
  Top 0.406: R18.1 17.27,37.08 v22.61,23.11 | v29.21,23.11 30.85,18.62
  Bottom 0.406: v22.61,23.11 v29.21,23.11
N$13
  Top 0.406: 29.16,32.21 arc90 29.15,32.22 | 29.16,32.21 arc-90 28.95,32.42 C3.1 28.95,37.42 arc90 28.91,37.46 arc-90 28.83,37.54 R2.1 | 29.16,32.21 29.21,32.26 35.81,17.02 arc-90 33.53,13.97 33.35,13.98 U$4.TD+
N$14
  Top 0.22: U$1.P$17 36.25,53.75 37.25,53.25 45,53 U$2.60
N$15  (1 unrouted)
  Top 0.22: 20.66,52.65 20.75,52.65 20.75,52.75 U$1.P$46
  Top 0.254: R4.1 18.91,51.12 18.91,51.46 19.66,51.46 arc90 20.66,52.46 20.66,52.65
  Top 0.61: 18.91,51.12 16.91,49.96 15.66,49.96 14.91,48.21 C4.1
N$16
  Top 0.22: U$1.P$18 37,54.25 arc-90 37.25,54 45,53.75 U$2.59
N$17
  Top 0.22: U$1.P$19 37.5,54.75 45,54.5 U$2.58
  Top 0.254: 44.71,54.56 arc90 44.74,54.53 U$2.58
N$18
  Top 0.22: U$2.57 45,55.25 U$1.P$20
  Top 0.254: U$2.57 44.91,55.36
N$19
  Top 0.22: U$1.P$21 34.5,55.75 arc90 34.75,56 45,56 arc-90 44.91,56.09 U$2.56
  Top 0.254: U$2.56 44.91,56.16
N$20
  Top 0.22: U$1.P$22 33.25,56.25 arc90 34,57 44.75,57 arc90 44.82,56.93 U$2.55
  Top 0.254: U$2.55 44.91,56.96
N$21
  Top 0.22: U$1.P$23 32.25,56.75 arc90 33.25,57.75 45,57.75 arc-90 44.98,57.73 U$2.54
  Top 0.254: U$2.54 44.91,57.76
N$22
  Top 0.22: U$1.P$39 21.75,56.25 arc-90 21,57 | 22,64.46 22,64.5
  Top 0.254: 21.66,64.46 22,64.46 22.25,64.46 | 22.25,64.46 38.66,64.46 arc-90 42.16,60.96 44.66,60.96 arc90 44.69,60.93 U$2.50 | 22.25,64.46 22.25,64.5 21,64.5 21,57
N$23
  Top 0.22: U$1.P$40 21.5,55.75 arc-90 19.75,57.5
  Top 0.254: U$2.49 arc90 41.39,65.25 19.75,65.25 19.75,57.5
N$24  (1 unrouted)
  Top 0.22: U$1.P$42 21,54.75 arc-90 20.75,55 19,56.5 18.75,58.25
  Top 0.254: U$2.48 46.66,63.46 arc103 44.66,65.96 18.75,66 18.75,58.25
N$26
  Top 0.22: U$1.P$3 24.75,49.25 arc-90 23.75,48.25 arc57 20.5,46.5
  Top 0.305: R18.2 17.25,40 20.5,46.5
N$27
  Top 0.254: U$7.MISO 54.24,35.13 arc90 54.16,35.21 arc90 56.31,37.36 U$2.13
N$28  (via drill 0.6)
  Top 0.305: v53.65,45.26 53.59,45.21 54.71,46.76
  Top 0.406: 54.71,46.76 U$2.11 | U$7.SCK 51.82,35.05 v51.56,32
  Bottom 0.406: v51.56,32 v53.65,45.26
N$29  (via drill 0.6)
  Top 0.254: 44.16,34.96 arc-90 44.12,34.92 U$7.MOSI
  Top 0.305: U$2.12 55.51,45.86 55.37,45.72 v54.86,43.69
  Top 0.406: 44.2,34.8 U$7.MOSI arc-90 44.2,34.8 | v44.96,31.75 arc-90 44.2,32.51 44.2,34.8
  Bottom 0.406: v54.86,43.69 53.09,30.48 48.77,30.48 v44.96,31.75
N$30  (via drill 0.6)
  Top 0.305: 60.54,52.16 61.38,52.16 arc-90 61.98,51.56 v63.5,50.04
  Top 0.406: 60.54,52.16 arc90 U$2.20 | U$7.RESETBAR arc-90 49.2,34.96 49.31,34.96 49.31,28.98 arc90 R6.1 49.28,28.96 v53.85,28.96
  Bottom 0.406: v53.85,28.96 v63.5,50.04
N$31
  Top 0.406: U$2.8 52.31,46.76 arc-90 51.91,46.36 51.91,45.16 arc-90 51.71,44.96 PAD16.1
N$32
  Top 0.22: 99.47,46.71 arc90 99.47,46.71 arc-90 99.47,46.71 | 99.47,46.71 99.41,46.71 | U$3.82 99.47,46.71
  Top 0.254: 99.41,46.71 arc90 100.41,47.71 100.66,47.96 108.91,47.96 arc-90 109.41,47.46 arc90 110.16,46.71 PAD33.1
  Top 0.406: PAD33.1 R7.2
N$33
  Top 0.22: U$3.83 98.62,47.21 arc90 99.5,48.09 99.5,48.3 arc-90 99.91,48.71 arc90 99.91,48.71
  Top 0.254: PAD32.1 111.91,48.71 99.91,48.71
  Top 0.406: R8.2 111.99,51.04 arc90 111.91,50.96 PAD32.1
N$34  (1 unrouted)
  Top 0.22: 24.66,60.46 24.71,60.46 arc90 24.75,60.5 arc-90 25.75,59.5 U$1.P$32
  Top 0.254: 24.66,60.46 24.66,62.71 arc-90 25.66,63.71 37.91,63.71 arc-90 41.41,60.21 44.66,60.21
  Top 0.406: U$2.51 45.08,60.13
N$35
  Top 0.22: 72.89,50.23 72.89,50.21 U$3.20
  Top 0.254: 60.41,56.96 U$2.26 60.66,56.96 63.91,56.96 72.89,50.23
N$36
  Top 0.22: 71.41,52.71 71.41,52.71 arc-90 71.41,52.71 U$3.15
  Top 0.254: 71.41,52.71 64.91,57.71 60.66,57.71 U$2.27
N$37  (1 unrouted)
  Top 0.22: 72.14,53.21 arc90 72.14,53.21 | 72.14,53.21 U$3.14 | 72.14,53.21 arc90 72.14,53.21
  Top 0.254: 72.12,53.25 65.66,58.46 60.66,58.46 U$2.28
N$38  (1 unrouted)
  Top 0.22: 80.66,62.96 80.65,62.96 80.65,61.46 80.66,61.46
  Top 0.254: U$2.44 49.91,65.21 arc-90 55.66,70.96 72.41,70.96 80.16,64.46 80.64,62.96 80.65,62.96
N$39
  Top 0.22: 79.66,63.71 79.66,63.72 | 79.64,63.71 79.66,63.71 | U$3.141 79.66,63.71
  Top 0.254: U$2.42 51.51,65.06 arc-90 56.66,70.21 71.91,70.21 79.64,63.71
N$40
  Top 0.22: 79.15,63.21 79.17,63.21 U$3.142
  Top 0.254: U$2.41 52.31,65.11 arc-90 56.66,69.46 71.41,69.46 79.15,63.21
N$41  (1 unrouted)
  Top 0.22: U$3.143 78.66,62.71
  Top 0.254: U$2.40 53.16,64.21 53.16,64.96 arc-90 56.91,68.71 71.16,68.71 78.63,62.68
N$42
  Top 0.22: U$1.P$6 26.25,45.5 arc-90 26,45.25 26,41.75 arc-90 25.5,41.25 arc-90 25.46,41.21 25.41,41.21
  Top 0.254: R3.1 R3.1 arc90 21.41,38.46 arc-90 24.16,41.21 25.41,41.21
  Top 0.406: 21.42,32.22 arc90 21.41,32.21 21.41,32.26 | 21.41,32.26 21.41,38.46 | 21.41,32.26 21.34,32.26 27.18,18.03 26.16,15.24 26.07,11.44 U$4.RD-
N$43
  Top 0.22: U$3.144 78.16,61.66 | U$3.144 | 77.66,62.21 78.16,62.21 U$3.144
  Top 0.254: U$2.39 53.91,64.71 arc-90 57.16,67.96 70.66,67.96 77.66,62.21
N$44
  Top 0.22: U$3.1 75.69,59.71 75.66,60.21
  Top 0.254: U$2.38 54.66,63.96 54.66,64.46 arc-90 57.41,67.21 64.41,67.21 68.16,63.46 75.66,60.21
N$45
  Top 0.22: U$3.2 75.15,59.21 arc-90 74.59,59.77 73.82,60.15 73.83,60.16
  Top 0.254: U$2.37 55.49,63.63 55.5,64.13 arc-90 57.66,66.46 63.91,66.46 67.6,62.83 73.83,60.16 73.85,60.15
N$46
  Top 0.22: 73.91,59.29 73.91,59.3 arc-90 73.92,59.31 arc90 74.52,58.71 U$3.3
  Top 0.254: U$2.36 56.3,63.73 56.3,64.47 arc-90 57.66,65.71 63.41,65.71 66.91,62.26 73.91,59.29
N$47
  Top 0.22: 72.92,58.98 72.95,58.98 arc90 73.72,58.21 U$3.4
  Top 0.254: U$2.35 57.11,64.66 57.41,64.96 62.91,64.96 66.41,61.46 72.92,58.98
N$48
  Top 0.406: U$2.14 57.11,45.9 57.92,45.09 57.92,44.41 57.96,44.38 PAD34.1
N$49
  Top 0.305: U$2.29 61.65,59.33 arc90 62.28,59.96 63.13,59.96 arc90 63.16,60 arc-90 63.19,60.02 PAD35.1
N$50
  Top 0.22: U$6.P$3 103.12,51.21 arc-90 103.12,51.21 U$3.91
  Top 0.254: U$6.P$3 arc-90 103.16,51.21
N$51
  Top 0.22: U$3.45 82.2,35.77 82.41,32.53 82.61,31.36 82.61,31.38
  Top 0.254: 82.61,31.38 arc90 83.28,30.93 85.23,30.93 U$5.11
N$52
  Top 0.22: 81.15,30.45 81.15,30.42 | 81.15,30.45 81.16,30.46 | U$3.43 81.15,30.45
  Top 0.254: 81.16,30.46 arc90 81.98,29.64 83.94,29.64 U$5.13
N$53
  Top 0.22: 88.66,31.76 88.67,31.62 U$3.58
  Top 0.254: 88.66,31.76 arc-90 88.16,31.26 arc90 87.83,30.93 U$5.7
N$54
  Top 0.22: 89.14,30.93 89.19,31.02 U$3.59
  Top 0.254: 89.16,30.93 89.14,30.93 arc-90 88.81,30.61 arc90 88.48,30.29 U$5.6
N$55
  Top 0.22: 91.66,32.71 91.68,32.71 U$3.64
  Top 0.254: 91.66,32.71 arc-101 91.08,32.23 90.11,32.23 arc90 89.78,31.91 89.78,30.61 arc-90 89.46,30.29 arc90 89.14,29.96 U$5.5
N$56
  Top 0.22: U$3.44 81.66,31.79 81.95,30.99 81.94,31
  Top 0.254: 81.94,31 arc90 82.64,30.29 84.58,30.29 U$5.12
N$57
  Top 0.22: 95.66,32.71 95.66,32.67 U$3.72
  Top 0.254: 95.66,32.71 arc-78 92.39,28.66 91.73,28.34 U$5.1
N$58
  Top 0.254: U$3.73 97.66,28.41 arc-20 96.61,22.48 R9.2
N$59
  Top 0.22: U$3.41 80.15,33.93 79.52,32.94 79.16,32.71
  Top 0.254: PAD51.1 79.16,32.71
N$60  (1 unrouted)
  Top 0.22: 85.74,35.93 U$3.52
  Top 0.254: U$5.9 86.53,32.23 85.77,36.03
N$61
  Top 0.22: 94.1,35.46 94.15,35.37 U$3.69
  Top 0.254: 94.1,35.46 arc-57 92.06,31.59 90.76,31.59 arc90 90.44,31.26 90.44,30.29 arc-90 89.78,29.64 U$5.4
N$62  (1 unrouted)
  Top 0.22: U$3.57 88.16,35.18 88.16,35.16 arc-180 88.12,35.16
  Top 0.254: U$5.8 87.19,31.59 arc-66 87.51,31.91 88.13,35.25
N$63
  Top 0.22: U$3.42 80.66,31.31 80.33,30.98 80.33,28.33 80.66,28.33 80.66,28.34
  Top 0.254: U$5.14 83.28,28.34 80.66,28.34
N$64
  Top 0.22: 85.17,34.95 U$3.51
  Top 0.254: U$5.10 85.89,31.59 85.56,31.59 arc-90 85.16,31.98 85.17,34.95 85.17,34.94
N$65
  Top 0.22: 94.66,34.96 94.66,34.97 U$3.70
  Top 0.254: 94.66,34.96 arc-52 92.71,30.93 91.41,30.93 arc90 91.08,30.61 91.08,30.29 90.44,28.98 U$5.3
N$66
  Top 0.22: U$3.71 95.18,33.65 arc-25 95.03,32.96 95.02,32.65
  Top 0.254: 95.02,32.65 arc-50 94.17,30.64 arc-27 91.73,29.64 arc64 91.08,28.98 arc26 91.08,28.34 U$5.2
N$67
  Top 0.254: 94.01,22.48 R9.1 91.76,22.48 arc-90 U$5.28
N$68
  Top 0.22: 72.41,49.71 72.39,49.71 U$3.21
  Top 0.254: 72.41,49.71 71.91,50.21 63.66,56.21 60.66,56.21 U$2.25
N$69
  Top 0.22: 66.01,46.21 65.92,46.21 | 65.92,46.21 U$3.28 | 65.92,46.21
  Top 0.254: 66.01,46.21 arc-90 61.76,50.46 60.56,50.46 arc-90 60.51,50.51 U$2.18
N$70
  Top 0.254: U$3.32 74.66,44.21 arc90 74.16,43.71 63.66,43.71 arc-90 59.66,47.71 58.91,47.71 arc-90 58.66,47.96 arc90 58.69,47.93 U$2.16
N$71  (1 unrouted)
  Top 0.305: U$5.17 84.58,21.51 arc-90 83.66,20.58 81.89,19.79 81.89,19.3 R15.1
  Top 0.61: R16.2 76.82,19.3 | 76.82,19.3 81.89,19.3 | 76.82,19.3 76.78,22.82
N$72
  Top 0.305: U$5.24 89.17,19.81 89.75,19.81 C14.1 91.38,19.79 91.38,16.29 | 91.43,15.74 91.5,15.75 PAD4.1
  Top 0.406: C12.+ 91.52,14.94 91.43,15.74 91.38,16.25 91.38,16.29
N$74
  Top 0.305: R14.1 85.22,19.2 U$5.18
N$75
  Top 0.254: U$5.21 87.16,22.51 87.16,13.96 PAD41.1
N$76
  Top 0.254: U$5.22 87.82,22.51 87.82,8.41 87.09,8.41 87.09,8.46 | 87.09,8.46 87.09,8.48 | PAD42.1 87.09,8.46
N$77
  Top 0.406: C19.1 PAD43.1
N$78
  Top 0.406: C22.1 PAD44.1
N$79
  Top 0.61: U$10.7 128.27,15.88 arc90 128.91,16.51 C29.1 128.27,19.56 PAD48.1 128.27,19.81 127.64,27.94 C31.+
N$80
  Top 0.61: R10.1 arc90 112.75,10.79 116.09,10.79 arc90 C24.1 arc90 116.2,10.9 116.2,12.51 | 116.2,12.51 116.2,12.7 | 116.2,12.51 arc-90 PAD45.1 116.84,12.7 117.47,13.97 arc-90 118.11,14.61 U$10.3
N$81  (1 unrouted)
  Top 0.305: 123.19,10.79 123.19,9.91 arc-90 123.18,9.9 arc90 123.17,9.91 PAD47.1 123.82,9.54 123.83,9.53
  Top 0.61: U$10.4 120.59,10.79 123.19,10.79 | C32.- 124.26,9.53 123.83,9.53
N$82
  Top 0.61: U$10.2 117.47,15.88 117.47,16.51 R12.2 118.11,16.51 118.11,18.41 arc-90 120.02,20.32 R11.2
N$83
  Top 0.406: R11.1 123.34,14.61 U$10.6
  Top 0.61: U$10.6 127,14.61 arc-67 128.91,13.34 R13.2
N$84
  Top 0.406: PAD49.1 47.51,44.78 U$2.2
N$86
  Top 0.305: PAD50.1 48.34,68.12 arc90 48.34,68.13 arc90 48.31,68.1 U$2.46
N$88  (1 unrouted)
  Bottom 0.61: C39.1 31.06,11.41
N$89
  Top 0.22: U$3.40 79.66,38.12 arc-90 78.84,37.29 78.84,35.62 arc90 78.85,35.61 arc-90 78.69,35.46 PAD52.1
N$90
  Top 0.22: U$3.74 98.66,42.71 arc-90 99.42,41.95 99.42,37.97 arc-90 PAD53.1 arc-90 PAD53.1
N$91
  Top 0.61: PAD54.1 135.18,13.46 R13.1
N$92
  Top 0.61: PAD40.1 76.85,13.88 R16.1
N$93  (1 unrouted)
  Bottom 0.61: C38.1 27.43,16.63 27.31,13.99
VCCINT  (via drill 0.6)  (2 unrouted)
  Top 0.22: 95.69,63.23 95.66,63.2 arc-90 95.64,63.19 arc-90 95.66,63.17 U$3.109 95.66,60.27 arc90 95.66,60.27 95.69,60.29 95.69,60.3 | 95.69,60.3 arc-90 95.69,60.3 | U$3.107 96.79,59.21 arc-90 95.69,60.3 | U$3.50 84.61,36.11 83.95,34.22 83.94,34.19 v83.92,34.18 | 78.16,41.46 78.16,41.46 arc-90 78.16,41.45 arc-90 78.16,41.45 U$3.37 | v101.82,46.5 101.52,46.22 U$3.81 | v90.46,36.98 90.66,37.3 U$3.62 | v73.76,41.7 v73.77,41.7 arc90 73.77,41.7 arc-90 74.78,42.71 75.16,42.71 | U$3.131 84.66,63.02 arc90 83.85,63.83 83.41,63.83 83.41,63.95 | U$3.124 v88.16,63.54 arc-90 88.11,63.59 88.11,63.87 arc42 87.37,65.78 C21.1 | C25.1 arc90 C25.1 83.41,63.95 | 83.41,63.95 83.37,63.95 v83.36,63.8 | U$3.26 74.78,47.21 arc-90 v73.79,48.21
  Top 0.254: 78.16,41.46 arc90 76.91,42.71 U$3.35 75.16,42.71 | C21.1 87.41,65.96 | C25.1 83.41,65.96 | 95.69,63.23 arc-90 96.66,64.21 96.91,64.21 | 71.41,41.46 71.41,41.71 C23.1
  Top 0.305: C27.1 103.81,46.48 arc90 103.78,46.5 v101.82,46.5 | C23.1 71.49,41.71 arc-90 71.48,41.72 arc90 71.5,41.7 v73.76,41.7 | v73.76,41.7 73.76,39.79 arc90 73.82,39.73 72.99,39.73 arc90 72.97,39.72 arc90 72.98,39.72 PAD19.1 | C26.1 v100.06,64.61 | v100.07,64.62 100.03,64.59 | v73.76,41.7 73.67,41.78 73.8,41.69 | v73.79,48.21 C28.1
  Bottom 0.22: v88.16,63.54 v83.36,63.8
  Bottom 0.305: v83.92,34.18 v83.92,34.17 arc-90 83.92,34.17 arc-90 83.95,34.14 83.95,34.1 | 83.95,34.1 C33.1 | 90.39,37.2 arc-90 90.43,37.23 v90.46,36.98 | C34.1 90.48,37.11 arc90 90.39,37.2 | 90.39,37.2 90.47,34.96 v83.92,34.19 v83.92,34.18 | v101.82,46.5 101.78,46.49 101.86,46.57 | 101.86,46.57 103.67,48.53 103.32,62.02 v100.07,64.62 100.07,64.6 96.11,66.3 90.92,66.3 v88.16,63.54 | v90.46,36.98 90.41,37.18 | v83.92,34.18 arc-90 83.84,34.1 | v73.79,48.21 73.79,41.71 arc-90 73.71,41.63 arc90 73.76,41.68 v73.76,41.7 73.71,41.67 83.95,34.1 | 101.86,46.57 94.93,35.09 91.91,35.09 91.91,35.17 arc-90 90.53,36.55 90.53,37.23 v90.46,36.98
